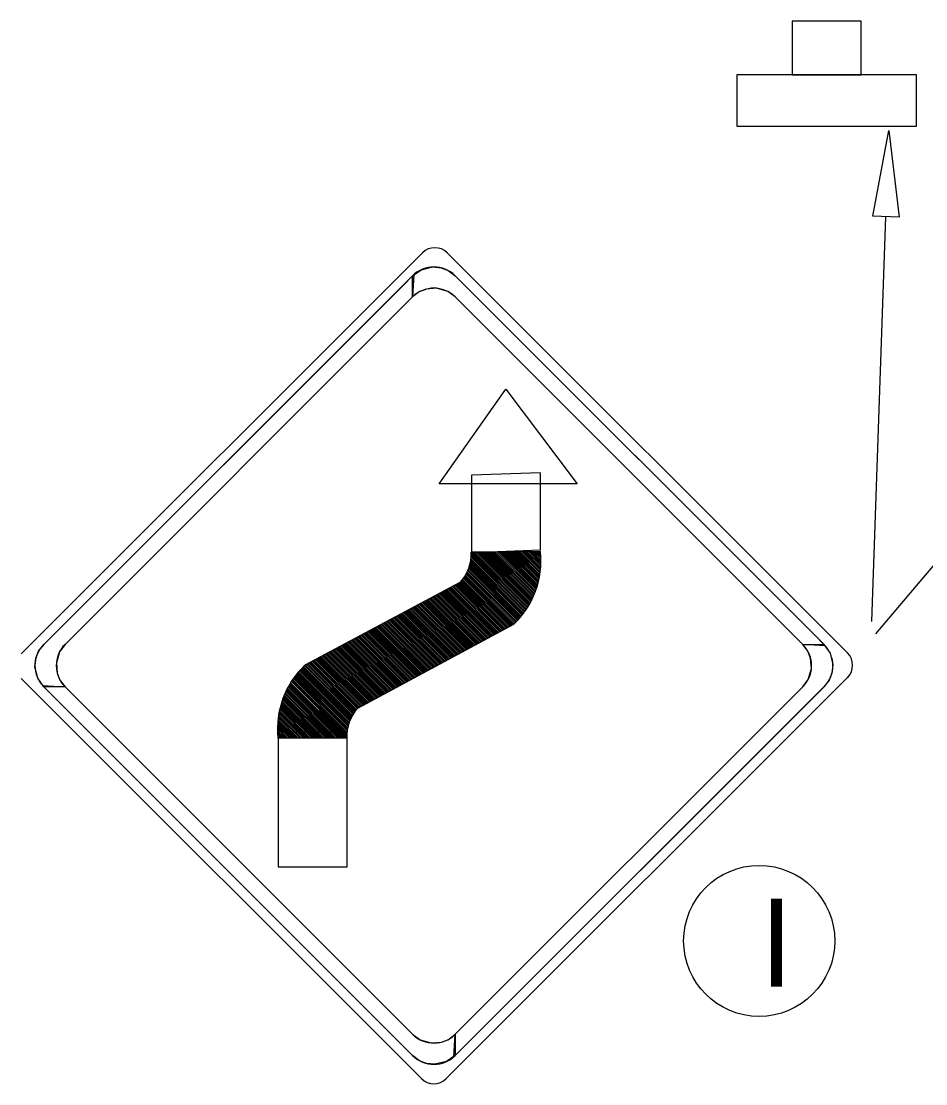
# Model space of a CAD drawing. Extents: x 1531.2 to 1538.6, y 1529.6 to 1539.7.
# Drawn here: x 1533.576 to 1534.399, y 1536.29 to 1537.257 of the extents above; entities that cross this region are included whole.
import ezdxf

# ---------------------------------------------------------------- set-up
doc = ezdxf.new("R2010")
doc.units = 0
for name, color, linetype in [('DETL-DIMS', 7, 'Continuous'), ('DETL-LINE', 7, 'Continuous'), ('DETL-NOTE', 7, 'Continuous')]:
    doc.layers.add(name, color=color, linetype=linetype)

msp = doc.modelspace()

# ---------------------------------------------------------------- linework, layer by layer
at = {"layer": 'DETL-DIMS'}
for p, q in [((1534.35327, 1536.69959), (1534.70894, 1537.12095)), ((1534.34968, 1536.71077), (1534.36255, 1537.07946))]:
    msp.add_line(p, q, dxfattribs=at)
msp.add_lwpolyline([(1534.36529, 1537.15789), (1534.37454, 1537.07904), (1534.35056, 1537.07988)], close=True, dxfattribs=at)
at = {"layer": 'DETL-LINE'}
for p, q in [((1533.94068, 1537.04658), (1533.5756, 1536.6815)), ((1534.32756, 1536.68234), (1533.96328, 1537.04658)), ((1533.59612, 1536.69006), (1533.9318, 1537.02578)), ((1533.97052, 1537.02578), (1534.30624, 1536.69006)), ((1533.93176, 1537.00642), (1533.61544, 1536.6901)), ((1534.28684, 1536.69006), (1533.97048, 1537.00642)), ((1534.04812, 1536.77458), (1533.98508, 1536.77394)), ((1534.03588, 1536.72322), (1533.98516, 1536.77394)), ((1534.03652, 1536.7241), (1533.98668, 1536.77394)), ((1534.03716, 1536.72506), (1533.9882, 1536.77394)), ((1534.03772, 1536.7261), (1533.9898, 1536.77394)), ((1534.03828, 1536.72706), (1533.99132, 1536.7741)), ((1534.03884, 1536.72802), (1533.99284, 1536.7741)), ((1534.03932, 1536.72906), (1533.99436, 1536.7741)), ((1534.03988, 1536.7301), (1533.99596, 1536.7741)), ((1534.04036, 1536.73114), (1533.99748, 1536.7741)), ((1534.04092, 1536.73218), (1533.999, 1536.7741)), ((1534.04148, 1536.73322), (1534.00052, 1536.77418)), ((1534.04188, 1536.73426), (1534.00212, 1536.77418)), ((1534.04236, 1536.73546), (1534.00364, 1536.77418)), ((1534.04276, 1536.7365), (1534.00516, 1536.77418)), ((1534.04324, 1536.73762), (1534.00668, 1536.77418)), ((1534.04364, 1536.73874), (1534.00828, 1536.77418)), ((1534.04412, 1536.73994), (1534.0098, 1536.77426)), ((1534.04444, 1536.74106), (1534.01132, 1536.77426)), ((1534.04492, 1536.74226), (1534.01284, 1536.77426)), ((1534.04524, 1536.74346), (1534.01444, 1536.77426)), ((1534.04556, 1536.74466), (1534.01596, 1536.77426)), ((1534.04596, 1536.74594), (1534.01748, 1536.77426)), ((1534.0462, 1536.74714), (1534.019, 1536.77434)), ((1534.04652, 1536.74834), (1534.0206, 1536.77434)), ((1534.04684, 1536.7497), (1534.02212, 1536.77434)), ((1534.04708, 1536.7509), (1534.02364, 1536.77434)), ((1534.04732, 1536.75226), (1534.02516, 1536.77434)), ((1534.04756, 1536.75354), (1534.02676, 1536.77434)), ((1534.0478, 1536.75498), (1534.02828, 1536.77442)), ((1534.04796, 1536.75626), (1534.0298, 1536.77442)), ((1534.04804, 1536.7577), (1534.0314, 1536.77442)), ((1534.0482, 1536.75914), (1534.03292, 1536.77442)), ((1534.04828, 1536.7605), (1534.03452, 1536.77442)), ((1534.04844, 1536.76202), (1534.03596, 1536.77442)), ((1534.04852, 1536.76354), (1534.03756, 1536.7745)), ((1534.0486, 1536.76498), (1534.03908, 1536.7745)), ((1534.0486, 1536.76658), (1534.04068, 1536.7745)), ((1534.0486, 1536.76818), (1534.04212, 1536.7745)), ((1534.04852, 1536.76978), (1534.04372, 1536.7745)), ((1534.04844, 1536.77146), (1534.04524, 1536.7745)), ((1534.04828, 1536.77306), (1534.04684, 1536.77458)), ((1534.0314, 1536.71674), (1533.98428, 1536.76402)), ((1534.03212, 1536.71762), (1533.98452, 1536.7653)), ((1534.03276, 1536.7185), (1533.98468, 1536.76658)), ((1534.03348, 1536.71938), (1533.98484, 1536.76802)), ((1534.03404, 1536.72042), (1533.98508, 1536.76938)), ((1534.0354, 1536.72226), (1533.98516, 1536.77242)), ((1534.03468, 1536.7213), (1533.98516, 1536.7709)), ((1534.02484, 1536.70938), (1533.98036, 1536.75386)), ((1534.02564, 1536.71018), (1533.98092, 1536.7549)), ((1534.02644, 1536.71098), (1533.9814, 1536.75586)), ((1534.02708, 1536.71178), (1533.98196, 1536.75698)), ((1534.02788, 1536.71258), (1533.98244, 1536.75802)), ((1534.0286, 1536.71346), (1533.98284, 1536.75922)), ((1534.02932, 1536.71426), (1533.98316, 1536.76034)), ((1534.03004, 1536.71514), (1533.98364, 1536.76146)), ((1534.03068, 1536.71586), (1533.98388, 1536.76274)), ((1533.9754, 1536.74674), (1533.8338, 1536.67122)), ((1534.013, 1536.7025), (1533.97108, 1536.7445)), ((1534.01412, 1536.70306), (1533.97212, 1536.74506)), ((1534.01508, 1536.70354), (1533.97308, 1536.74554)), ((1534.01612, 1536.7041), (1533.97412, 1536.7461)), ((1534.01708, 1536.70474), (1533.97508, 1536.74658)), ((1534.01812, 1536.70522), (1533.97588, 1536.74738)), ((1534.01908, 1536.70578), (1533.97668, 1536.74826)), ((1534.02012, 1536.70634), (1533.97732, 1536.74914)), ((1534.02116, 1536.70682), (1533.97804, 1536.75002)), ((1534.0222, 1536.70746), (1533.9786, 1536.7509)), ((1534.02316, 1536.70794), (1533.97924, 1536.75186)), ((1534.02404, 1536.70858), (1533.97988, 1536.75282)), ((1533.99484, 1536.69274), (1533.95284, 1536.73474)), ((1533.99588, 1536.6933), (1533.9538, 1536.73522)), ((1533.99684, 1536.69378), (1533.95484, 1536.73578)), ((1533.99788, 1536.69434), (1533.9558, 1536.73642)), ((1533.99884, 1536.6949), (1533.95692, 1536.7369)), ((1533.99988, 1536.69538), (1533.95796, 1536.73746)), ((1534.00092, 1536.69602), (1533.95892, 1536.73802)), ((1534.00196, 1536.6965), (1533.95996, 1536.7385)), ((1534.00292, 1536.69706), (1533.96092, 1536.73906)), ((1534.00396, 1536.69762), (1533.96196, 1536.73954)), ((1534.00492, 1536.6981), (1533.96292, 1536.74018)), ((1534.00596, 1536.69874), (1533.96404, 1536.74074)), ((1534.00692, 1536.6993), (1533.965, 1536.74122)), ((1534.00804, 1536.69978), (1533.96604, 1536.74178)), ((1534.009, 1536.70034), (1533.967, 1536.74226)), ((1534.01004, 1536.70082), (1533.96804, 1536.74282)), ((1534.011, 1536.70138), (1533.969, 1536.74338)), ((1534.01204, 1536.70202), (1533.97012, 1536.74394)), ((1533.97668, 1536.6829), (1533.93452, 1536.72498)), ((1533.97764, 1536.68346), (1533.93556, 1536.72554)), ((1533.97868, 1536.68402), (1533.93652, 1536.7261)), ((1533.97964, 1536.68458), (1533.93764, 1536.72666)), ((1533.98076, 1536.68506), (1533.9386, 1536.72714)), ((1533.98172, 1536.68562), (1533.93964, 1536.7277)), ((1533.98268, 1536.68618), (1533.94068, 1536.72818)), ((1533.98372, 1536.68666), (1533.94164, 1536.72874)), ((1533.98468, 1536.6873), (1533.94268, 1536.72938)), ((1533.98572, 1536.68786), (1533.94372, 1536.72986)), ((1533.98668, 1536.68834), (1533.94476, 1536.73042)), ((1533.9878, 1536.6889), (1533.94572, 1536.73098)), ((1533.98876, 1536.68938), (1533.94676, 1536.73146)), ((1533.9898, 1536.69002), (1533.94772, 1536.73202)), ((1533.99076, 1536.69058), (1533.94876, 1536.7325)), ((1533.9918, 1536.69106), (1533.94972, 1536.73314)), ((1533.99276, 1536.69162), (1533.95084, 1536.7337)), ((1533.99388, 1536.6921), (1533.9518, 1536.73418)), ((1533.95844, 1536.67314), (1533.91628, 1536.7153)), ((1533.9594, 1536.67362), (1533.91732, 1536.71578)), ((1533.96052, 1536.67418), (1533.91836, 1536.71634)), ((1533.96148, 1536.67474), (1533.91932, 1536.7169)), ((1533.96252, 1536.6753), (1533.92036, 1536.71738)), ((1533.96348, 1536.67586), (1533.9214, 1536.71794)), ((1533.96452, 1536.67642), (1533.92236, 1536.7185)), ((1533.96548, 1536.6769), (1533.92348, 1536.71906)), ((1533.9666, 1536.67746), (1533.92444, 1536.71962)), ((1533.96756, 1536.67802), (1533.92548, 1536.7201)), ((1533.9686, 1536.67858), (1533.92644, 1536.72066)), ((1533.96956, 1536.67914), (1533.92748, 1536.72114)), ((1533.9706, 1536.67962), (1533.92844, 1536.7217)), ((1533.97156, 1536.68018), (1533.92948, 1536.72234)), ((1533.9726, 1536.68066), (1533.93052, 1536.72282)), ((1533.97364, 1536.6813), (1533.93156, 1536.72338)), ((1533.97468, 1536.68186), (1533.93252, 1536.72394)), ((1533.97564, 1536.68234), (1533.93356, 1536.72442)), ((1534.02356, 1536.70818), (1533.88164, 1536.63178)), ((1533.94028, 1536.66338), (1533.89804, 1536.70554)), ((1533.94124, 1536.66386), (1533.89908, 1536.70602)), ((1533.94228, 1536.66442), (1533.90004, 1536.70658)), ((1533.94324, 1536.66498), (1533.90108, 1536.70706)), ((1533.94428, 1536.66546), (1533.90204, 1536.7077)), ((1533.94524, 1536.66602), (1533.90308, 1536.70826)), ((1533.94636, 1536.66658), (1533.9042, 1536.70874)), ((1533.94732, 1536.66714), (1533.90516, 1536.7093)), ((1533.94836, 1536.6677), (1533.9062, 1536.70986)), ((1533.94932, 1536.66818), (1533.90716, 1536.71034)), ((1533.95036, 1536.66874), (1533.9082, 1536.7109)), ((1533.95132, 1536.66938), (1533.90916, 1536.71146)), ((1533.95236, 1536.66986), (1533.91028, 1536.71202)), ((1533.9534, 1536.67042), (1533.91124, 1536.71258)), ((1533.95444, 1536.6709), (1533.91228, 1536.71306)), ((1533.9554, 1536.67146), (1533.91324, 1536.71362)), ((1533.95644, 1536.6721), (1533.91428, 1536.7141)), ((1533.9574, 1536.67258), (1533.91524, 1536.71474)), ((1533.92204, 1536.65354), (1533.8798, 1536.69578)), ((1533.923, 1536.65402), (1533.88076, 1536.69626)), ((1533.92404, 1536.65466), (1533.8818, 1536.6969)), ((1533.925, 1536.65514), (1533.88276, 1536.69738)), ((1533.92612, 1536.6557), (1533.88388, 1536.69794)), ((1533.92708, 1536.65626), (1533.88492, 1536.6985)), ((1533.92812, 1536.65674), (1533.88588, 1536.69898)), ((1533.92908, 1536.65738), (1533.88692, 1536.69954)), ((1533.93012, 1536.65794), (1533.88788, 1536.70002)), ((1533.93108, 1536.65842), (1533.88892, 1536.70066)), ((1533.93212, 1536.65898), (1533.88988, 1536.70122)), ((1533.93316, 1536.65946), (1533.891, 1536.7017)), ((1533.9342, 1536.66002), (1533.89196, 1536.70226)), ((1533.93516, 1536.66066), (1533.893, 1536.70282)), ((1533.9362, 1536.66114), (1533.89396, 1536.7033)), ((1533.93716, 1536.6617), (1533.895, 1536.70394)), ((1533.9382, 1536.66218), (1533.89596, 1536.70442)), ((1533.93916, 1536.66274), (1533.89708, 1536.70498)), ((1533.9038, 1536.6437), (1533.86148, 1536.6861)), ((1533.90484, 1536.64426), (1533.86252, 1536.68658)), ((1533.90588, 1536.64482), (1533.86348, 1536.68714)), ((1533.90692, 1536.6453), (1533.8646, 1536.68762)), ((1533.90788, 1536.64594), (1533.86564, 1536.68818)), ((1533.90884, 1536.6465), (1533.8666, 1536.68874)), ((1533.90988, 1536.64698), (1533.86764, 1536.68922)), ((1533.91084, 1536.64754), (1533.8686, 1536.68986)), ((1533.91188, 1536.64802), (1533.86964, 1536.69034)), ((1533.91292, 1536.64866), (1533.87068, 1536.6909)), ((1533.91396, 1536.64922), (1533.87172, 1536.69146)), ((1533.91492, 1536.6497), (1533.87268, 1536.69194)), ((1533.91596, 1536.65026), (1533.87372, 1536.6925)), ((1533.91692, 1536.65074), (1533.87468, 1536.69298)), ((1533.91796, 1536.6513), (1533.87572, 1536.69362)), ((1533.91892, 1536.65194), (1533.87668, 1536.69418)), ((1533.92004, 1536.65242), (1533.8778, 1536.69466)), ((1533.921, 1536.65298), (1533.87876, 1536.69522)), ((1533.88668, 1536.6345), (1533.84428, 1536.67682)), ((1533.88764, 1536.63506), (1533.84532, 1536.67738)), ((1533.88868, 1536.63554), (1533.84628, 1536.67786)), ((1533.88964, 1536.6361), (1533.84732, 1536.67842)), ((1533.89068, 1536.63666), (1533.84836, 1536.67906)), ((1533.89164, 1536.63722), (1533.84932, 1536.67954)), ((1533.89276, 1536.63778), (1533.85044, 1536.6801)), ((1533.89372, 1536.63826), (1533.8514, 1536.68058)), ((1533.89476, 1536.63882), (1533.85244, 1536.68114)), ((1533.89572, 1536.6393), (1533.8534, 1536.6817)), ((1533.89676, 1536.63994), (1533.85444, 1536.68218)), ((1533.89772, 1536.6405), (1533.8554, 1536.68282)), ((1533.89884, 1536.64098), (1533.85644, 1536.6833)), ((1533.8998, 1536.64154), (1533.85748, 1536.68386)), ((1533.90084, 1536.6421), (1533.85852, 1536.68442)), ((1533.9018, 1536.64266), (1533.85948, 1536.6849)), ((1533.90284, 1536.64322), (1533.86052, 1536.68546)), ((1533.87492, 1536.6213), (1533.82948, 1536.66682)), ((1533.8754, 1536.62234), (1533.8302, 1536.66762)), ((1533.87596, 1536.62338), (1533.83092, 1536.66834)), ((1533.87644, 1536.6245), (1533.83172, 1536.66914)), ((1533.877, 1536.62546), (1533.83244, 1536.66994)), ((1533.87756, 1536.62642), (1533.83324, 1536.67074)), ((1533.8782, 1536.62738), (1533.83412, 1536.67138)), ((1533.87884, 1536.62826), (1533.83516, 1536.67202)), ((1533.87948, 1536.62922), (1533.83612, 1536.6725)), ((1533.88012, 1536.6301), (1533.83724, 1536.67306)), ((1533.88084, 1536.6309), (1533.8382, 1536.67354)), ((1533.88156, 1536.63178), (1533.83924, 1536.6741)), ((1533.8826, 1536.63226), (1533.8402, 1536.67466)), ((1533.88356, 1536.63282), (1533.84124, 1536.67522)), ((1533.8846, 1536.63338), (1533.8422, 1536.67578)), ((1533.88564, 1536.63394), (1533.84324, 1536.67626)), ((1533.5756, 1536.65894), (1533.93984, 1536.29466)), ((1533.87188, 1536.60722), (1533.82196, 1536.65714)), ((1533.87196, 1536.60874), (1533.8226, 1536.6581)), ((1533.87204, 1536.6101), (1533.82324, 1536.65898)), ((1533.8722, 1536.61154), (1533.82388, 1536.65986)), ((1533.87244, 1536.61282), (1533.82452, 1536.66082)), ((1533.87268, 1536.61418), (1533.82524, 1536.6617)), ((1533.873, 1536.61546), (1533.82588, 1536.66258)), ((1533.87332, 1536.61674), (1533.82652, 1536.66346)), ((1533.87364, 1536.61786), (1533.82724, 1536.66426)), ((1533.87404, 1536.61898), (1533.82796, 1536.66514)), ((1533.87452, 1536.62018), (1533.82868, 1536.66594)), ((1533.96244, 1536.29466), (1534.32756, 1536.65978)), ((1533.9318, 1536.31562), (1533.59612, 1536.65134)), ((1533.61544, 1536.65134), (1533.93176, 1536.33498)), ((1533.86044, 1536.60466), (1533.81684, 1536.64826)), ((1533.86204, 1536.60458), (1533.8174, 1536.64922)), ((1533.86364, 1536.60458), (1533.81796, 1536.65026)), ((1533.86516, 1536.60458), (1533.81844, 1536.6513)), ((1533.86668, 1536.60458), (1533.81908, 1536.65226)), ((1533.86828, 1536.60458), (1533.81964, 1536.65322)), ((1533.86988, 1536.60458), (1533.8202, 1536.65418)), ((1533.8714, 1536.60458), (1533.82076, 1536.65514)), ((1533.87188, 1536.6057), (1533.8214, 1536.65618)), ((1534.30624, 1536.65134), (1533.97052, 1536.31562)), ((1533.97052, 1536.33498), (1534.28684, 1536.65134)), ((1533.84644, 1536.60466), (1533.81284, 1536.63826)), ((1533.84804, 1536.60466), (1533.81324, 1536.63946)), ((1533.84956, 1536.60466), (1533.81364, 1536.64058)), ((1533.85108, 1536.60466), (1533.81404, 1536.6417)), ((1533.85268, 1536.60466), (1533.81452, 1536.64274)), ((1533.8542, 1536.60466), (1533.81492, 1536.64394)), ((1533.8558, 1536.60466), (1533.81548, 1536.64498)), ((1533.85732, 1536.60466), (1533.81588, 1536.6461)), ((1533.85892, 1536.60466), (1533.81644, 1536.64714)), ((1533.83396, 1536.60474), (1533.81028, 1536.62842)), ((1533.83556, 1536.60474), (1533.81052, 1536.62962)), ((1533.837, 1536.60474), (1533.81084, 1536.63098)), ((1533.8386, 1536.60474), (1533.81116, 1536.63218)), ((1533.8402, 1536.60466), (1533.8114, 1536.63346)), ((1533.8418, 1536.60466), (1533.8118, 1536.63466)), ((1533.84324, 1536.60466), (1533.81212, 1536.63594)), ((1533.84484, 1536.60466), (1533.81244, 1536.63706)), ((1533.823, 1536.60474), (1533.80908, 1536.61874)), ((1533.82452, 1536.60474), (1533.80916, 1536.62026)), ((1533.82612, 1536.60474), (1533.80924, 1536.62162)), ((1533.82772, 1536.60474), (1533.8094, 1536.62306)), ((1533.82932, 1536.60474), (1533.80956, 1536.62434)), ((1533.83076, 1536.60474), (1533.8098, 1536.6257)), ((1533.83236, 1536.60474), (1533.81004, 1536.62714)), ((1533.81828, 1536.60474), (1533.80876, 1536.61426)), ((1533.81676, 1536.60474), (1533.80876, 1536.61274)), ((1533.81524, 1536.60482), (1533.80876, 1536.61114)), ((1533.82148, 1536.60474), (1533.80884, 1536.6173)), ((1533.81988, 1536.60474), (1533.80884, 1536.61586)), ((1533.81364, 1536.60482), (1533.80884, 1536.60962)), ((1533.81204, 1536.60482), (1533.80892, 1536.60794)), ((1533.81052, 1536.60482), (1533.80916, 1536.60626)), ((1533.87188, 1536.60458), (1533.80924, 1536.60482))]:
    msp.add_line(p, q, dxfattribs=at)
for points in [[(1534.34007, 1537.2575), (1534.27715, 1537.2575), (1534.27715, 1537.20878), (1534.34007, 1537.20878)], [(1534.22683, 1537.20878), (1534.22683, 1537.16182), (1534.39035, 1537.16182), (1534.39035, 1537.20878)], [(1533.59612, 1536.69006), (1533.92216, 1537.01606), (1533.933, 1537.0269), (1533.93176, 1537.00642), (1533.61544, 1536.6901), (1533.61044, 1536.68326), (1533.60752, 1536.67314), (1533.60832, 1536.66386), (1533.61084, 1536.65746), (1533.61544, 1536.65134), (1533.59612, 1536.65134), (1533.5906, 1536.65918), (1533.58808, 1536.6697), (1533.58892, 1536.67742), (1533.59136, 1536.68378)], [(1533.97048, 1537.02574), (1534.29648, 1536.6997), (1534.30732, 1536.68886), (1534.28684, 1536.69006), (1533.97052, 1537.00642), (1533.96368, 1537.01142), (1533.95356, 1537.0143), (1533.94428, 1537.01354), (1533.93788, 1537.01102), (1533.93176, 1537.00642), (1533.93176, 1537.02574), (1533.93964, 1537.03122), (1533.95012, 1537.03374), (1533.95784, 1537.03294), (1533.9642, 1537.03046)], [(1534.01668, 1536.92242), (1534.08156, 1536.83634), (1533.95596, 1536.83634)], [(1534.04812, 1536.84634), (1533.98532, 1536.84402), (1533.98532, 1536.77386), (1534.04812, 1536.7761)], [(1534.30616, 1536.65134), (1533.98012, 1536.32534), (1533.96928, 1536.3145), (1533.97048, 1536.33498), (1534.28684, 1536.6513), (1534.29184, 1536.65814), (1534.29476, 1536.66826), (1534.29396, 1536.67754), (1534.29144, 1536.68394), (1534.28684, 1536.69006), (1534.30616, 1536.69006), (1534.31168, 1536.68222), (1534.3142, 1536.6717), (1534.31336, 1536.66398), (1534.31088, 1536.65762)], [(1533.93176, 1536.31566), (1533.6058, 1536.6417), (1533.59492, 1536.65254), (1533.61544, 1536.65134), (1533.93172, 1536.33498), (1533.9386, 1536.33002), (1533.94872, 1536.3271), (1533.958, 1536.32786), (1533.96436, 1536.33038), (1533.97048, 1536.33498), (1533.97048, 1536.31566), (1533.96264, 1536.31018), (1533.95212, 1536.30766), (1533.9444, 1536.30846), (1533.93808, 1536.31094)], [(1533.87212, 1536.48754), (1533.87212, 1536.61002), (1533.80932, 1536.61002), (1533.80932, 1536.48754)]]:
    msp.add_lwpolyline(points, close=True, dxfattribs=at)
for centre, radius, start, end in [((1533.95197, 1537.03531), 0.01598, 45, 135), ((1533.95117, 1537.0064), 0.02739, 45, 135), ((1533.95113, 1536.98705), 0.02739, 45, 135), ((1533.94699, 1536.77224), 0.03815, 318.09041, 2.58647), ((1533.96838, 1536.76632), 0.08018, 313.50136, 5.89922), ((1533.61546, 1536.6707), 0.02739, 135, 225), ((1533.6348, 1536.67072), 0.02739, 135, 225), ((1534.26749, 1536.67069), 0.02739, 315, 45), ((1534.28688, 1536.67069), 0.02739, 315, 45), ((1534.31624, 1536.67104), 0.01598, 315, 45), ((1533.88898, 1536.61306), 0.08018, 133.50136, 185.89922), ((1533.91001, 1536.6063), 0.03815, 138.09041, 182.58647), ((1533.95116, 1536.35436), 0.02739, 225, 315), ((1533.95117, 1536.33498), 0.02739, 225, 315), ((1533.95115, 1536.30596), 0.01598, 225, 315)]:
    msp.add_arc(centre, radius, start, end, dxfattribs=at)
at = {"layer": 'DETL-NOTE'}
msp.add_circle((1534.24719, 1536.42005), 0.06875, dxfattribs=at)

# ---------------------------------------------------------------- texts
msp.add_text('I', height=0.08, dxfattribs=at).set_placement((1534.24796, 1536.37838))

doc.saveas('drawing.dxf')
